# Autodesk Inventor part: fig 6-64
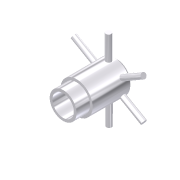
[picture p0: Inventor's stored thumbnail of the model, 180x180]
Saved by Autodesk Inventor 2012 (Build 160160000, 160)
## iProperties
Shininess: 77.0
Angle Display Precision: 2
Document Length Units: 11269
Document Angle Units: 11279
Document Time Units: 11290
Document Mass Units: 11283
Document Length Units Precision: 3
Document Angle Units Precision: 2
Compacted: True
Created: 2001-12
Part Number: fig 6-64
Document SubType Name: Modeling
Designer: Renu Muthoo
Density: 1 g/cm^3
Material: Default
Density: 0.0
Volumn: 0.0
Area: 0.0
PropertySet Name: Model Information
Control State: 0
Master: False
Checked Out: False
Author: Renu Muthoo
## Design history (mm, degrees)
sketch "Sketch2"
  geometry: L1 (-9.573, -4.327)-(-9.573, -5.327); L2 (-9.573, -5.327)-(-4.573, -5.327); L3 (-4.573, -5.327)-(-4.573, -6.327); L4 (-4.573, -6.327)-(9.427, -6.327); L5 (9.427, -6.327)-(10.427, -5.327); L6 (10.427, -5.327)-(10.427, -4.327); L7 (10.427, -4.327)-(-9.573, -4.327); L8 (-13.687, -0.327)-(14, -0.327)
  constraints: 16 end point, 5 parallel, 1 perpendicular, 1 vertical
  dimensions: "d9" = 20 distance of L6.end L1.start; "d10" = 5 distance of L1.end L2.end; "d11" = 12 diameter of L4 L8; "d12" = 10 diameter of L2 L8; "d13" = 8 diameter of L7 L8; "d14" = 45 deg angle of L5 L4; "d15" = 1 horizontal distance of L5.end L4.end
revolve "Revolution2" sketch "Sketch2" stored, may be unused: angle "d16" = 90 deg
workplane "Work Plane1"
workplane "Work Plane2"
sketch "Sketch3"
  geometry: L1 (-4, 8)-(4, 8) reference; C1 r 1 at (-0.098, 5)
  constraints: 1 centre point
  dimensions: "d18" = 3 distance from line of L1 C1.centre; "d19" = 2 diameter of C1
extrude "Extrusion1" join sketch "Sketch3" distance "d20" = 10; taper "d21" = 0 deg
pattern_circular "Circular Pattern3" dims angle "d29" = 360 deg
body "Solid1"
other parameters: "d17" = -1
